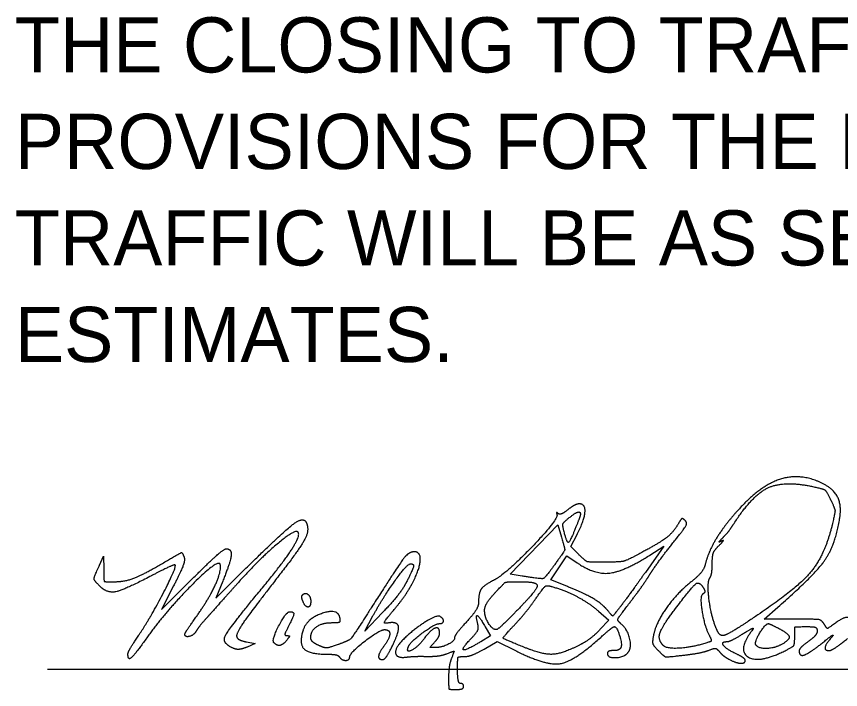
# Model space of a CAD drawing. Extents: x 0 to 34, y -7.5 to 22.
# Drawn here: x 24.421 to 26.511, y 8.312 to 10.02 of the extents above; entities that cross this region are included whole.
import ezdxf

# ---------------------------------------------------------------- set-up
doc = ezdxf.new("R2010")
doc.units = 0
doc.layers.add('SH_Data', color=7, linetype='Continuous')
doc.layers.add('SH_Text', color=7, linetype='Continuous')

msp = doc.modelspace()

# ---------------------------------------------------------------- linework, layer by layer
at = {"layer": 'SH_Data'}
msp.add_line((24.5, 8.3631), (28, 8.3631), dxfattribs=at)
at = {"layer": 'SH_Text'}
for p, q in [((25.1473, 8.5361), (25.1473, 8.5361)), ((25.074, 8.4303), (25.074, 8.4303)), ((24.7038, 8.402), (24.7038, 8.402))]:
    msp.add_line(p, q, dxfattribs=at)
for points in [[(25.7032, 8.5995), (25.6728, 8.6043), (25.7937, 8.73), (25.8032, 8.6979)], [(25.8471, 8.6544), (25.8273, 8.6743), (25.8431, 8.7054)], [(26.0277, 8.6528), (26.0627, 8.6751), (26.016, 8.609)], [(24.6314, 8.627), (24.6418, 8.6498), (24.6424, 8.6175)], [(25.8166, 8.5737), (25.7763, 8.5901), (25.7968, 8.6205), (25.8172, 8.6508), (25.8431, 8.6332)], [(24.9443, 8.5869), (24.9263, 8.5434), (25.0032, 8.6194)], [(24.8197, 8.5749), (24.7885, 8.5143), (24.866, 8.5915)], [(25.3498, 8.5073), (25.3044, 8.4598), (25.3252, 8.4984)], [(25.897, 8.5107), (25.9236, 8.4877), (25.9008, 8.4636)], [(26.3894, 8.4902), (26.3173, 8.4902), (26.352, 8.5206)], [(25.6099, 8.4709), (25.623, 8.4479), (25.5985, 8.433)], [(25.0047, 8.4325), (25.0268, 8.428), (25.006, 8.4194)], [(25.6073, 8.4144), (25.6406, 8.4334), (25.6864, 8.4105)]]:
    msp.add_lwpolyline(points, dxfattribs=at)
for points in [[(26.467, 8.8338), (26.4102, 8.8623), (26.3049, 8.8281), (26.2472, 8.7626)], [(26.239, 8.7302), (26.2861, 8.8038), (26.3666, 8.8426), (26.44, 8.8269)], [(26.44, 8.8269), (26.4676, 8.821), (26.4755, 8.8152), (26.486, 8.7931)], [(26.5088, 8.7448), (26.5142, 8.7776), (26.4942, 8.8203), (26.467, 8.8338)], [(25.8487, 8.7828), (25.843, 8.7828), (25.8297, 8.776), (25.8193, 8.7678)], [(25.8431, 8.7054), (25.8614, 8.7413), (25.8644, 8.7828), (25.8487, 8.7828)], [(26.486, 8.7931), (26.4968, 8.7704), (26.4973, 8.7609), (26.4897, 8.729)], [(25.7948, 8.7583), (25.7918, 8.7613), (25.7905, 8.7601), (25.7919, 8.7555)], [(25.8193, 8.7678), (25.8088, 8.7596), (25.7978, 8.7553), (25.7948, 8.7583)], [(25.8213, 8.7465), (25.8372, 8.7594), (25.8514, 8.764), (25.8514, 8.7563)], [(26.2472, 8.7626), (26.2136, 8.7244), (26.1756, 8.6606), (26.168, 8.6295)], [(25.0032, 8.6194), (25.0977, 8.7126), (25.1501, 8.7515), (25.157, 8.7335)], [(25.7919, 8.7555), (25.7955, 8.7438), (25.6624, 8.6049), (25.6332, 8.5899)], [(25.8099, 8.7123), (25.8058, 8.7284), (25.8084, 8.7361), (25.8213, 8.7465)], [(25.8514, 8.7563), (25.8514, 8.7543), (25.8459, 8.7389), (25.8392, 8.7221)], [(26.0861, 8.6836), (26.114, 8.7183), (26.1229, 8.7347), (26.1171, 8.7405)], [(26.1171, 8.7405), (26.1113, 8.7462), (26.1067, 8.7447), (26.1013, 8.7352)], [(26.352, 8.5206), (26.4443, 8.6012), (26.4977, 8.6776), (26.5088, 8.7448)], [(25.157, 8.7335), (25.164, 8.7155), (25.1419, 8.6722), (25.0952, 8.6118)], [(25.8392, 8.7221), (25.8249, 8.6863), (25.8171, 8.6837), (25.8099, 8.7123)], [(26.1013, 8.7352), (26.0882, 8.712), (26.055, 8.6852), (26.0075, 8.6597)], [(26.2124, 8.697), (26.2208, 8.7054), (26.2328, 8.7204), (26.239, 8.7302)], [(26.4897, 8.729), (26.4708, 8.6504), (26.3943, 8.5624), (26.278, 8.4854)], [(25.135, 8.7113), (25.1273, 8.719), (25.0363, 8.642), (24.9838, 8.5833)], [(25.0419, 8.5662), (25.0961, 8.6316), (25.1425, 8.7039), (25.135, 8.7113)], [(25.8032, 8.6979), (25.8124, 8.6669), (25.8118, 8.6645), (25.7879, 8.6312)], [(26.2086, 8.6878), (26.2024, 8.6844), (26.2041, 8.6886), (26.2124, 8.697)], [(26.0278, 8.6043), (26.0383, 8.621), (26.0646, 8.6567), (26.0861, 8.6836)], [(26.1857, 8.6324), (26.1858, 8.6515), (26.1913, 8.6659), (26.2029, 8.6772)], [(26.2029, 8.6772), (26.2123, 8.6863), (26.2149, 8.6911), (26.2086, 8.6878)], [(24.804, 8.6392), (24.8369, 8.6586), (24.8417, 8.6596), (24.846, 8.6483)], [(24.866, 8.5915), (24.9086, 8.634), (24.9477, 8.6688), (24.9529, 8.6688)], [(24.9529, 8.6688), (24.9675, 8.6688), (24.9639, 8.6346), (24.9443, 8.5869)], [(25.43, 8.6612), (25.416, 8.6612), (25.3902, 8.6276), (25.3225, 8.5215)], [(25.4251, 8.5813), (25.4438, 8.6169), (25.4466, 8.6612), (25.43, 8.6612)], [(25.8431, 8.6332), (25.8873, 8.603), (25.9615, 8.6109), (26.0277, 8.6528)], [(25.9143, 8.6348), (25.8733, 8.6346), (25.8644, 8.6372), (25.8471, 8.6544)], [(26.0075, 8.6597), (25.9701, 8.6396), (25.9529, 8.635), (25.9143, 8.6348)], [(24.6687, 8.5852), (24.6965, 8.5852), (24.7456, 8.6047), (24.804, 8.6392)], [(24.938, 8.6287), (24.9348, 8.6455), (24.8011, 8.5121), (24.7516, 8.4427)], [(24.846, 8.6483), (24.849, 8.6406), (24.8386, 8.6117), (24.8197, 8.5749)], [(25.7879, 8.6312), (25.7619, 8.5949), (25.753, 8.5916), (25.7032, 8.5995)], [(26.1794, 8.5944), (26.1828, 8.5998), (26.1857, 8.6169), (26.1857, 8.6324)], [(24.6329, 8.5735), (24.6178, 8.5887), (24.6176, 8.5968), (24.6314, 8.627)], [(24.6424, 8.6175), (24.643, 8.586), (24.6437, 8.5852), (24.6687, 8.5852)], [(24.7313, 8.4495), (24.761, 8.4937), (24.8281, 8.623), (24.8236, 8.6275)], [(24.8236, 8.6275), (24.8221, 8.6291), (24.7952, 8.6169), (24.7638, 8.6005)], [(24.8747, 8.4928), (24.9076, 8.5386), (24.9414, 8.6112), (24.938, 8.6287)], [(25.0952, 8.6118), (25.0175, 8.5114), (24.9771, 8.4531), (24.9798, 8.445)], [(25.3252, 8.4984), (25.3497, 8.5438), (25.4119, 8.6306), (25.4201, 8.6307)], [(25.4201, 8.6307), (25.4296, 8.6308), (25.4266, 8.6165), (25.4105, 8.5849)], [(26.168, 8.6295), (26.1653, 8.6184), (26.1492, 8.5983), (26.1323, 8.5849)], [(24.7638, 8.6005), (24.6945, 8.5642), (24.6512, 8.5553), (24.6329, 8.5735)], [(25.6332, 8.5899), (25.6065, 8.5763), (25.593, 8.557), (25.593, 8.5323)], [(26.016, 8.609), (25.9903, 8.5727), (25.9619, 8.5337), (25.9529, 8.5223)], [(25.9758, 8.5309), (25.9939, 8.5545), (26.0173, 8.5875), (26.0278, 8.6043)], [(26.1947, 8.4693), (26.1824, 8.5008), (26.1723, 8.5832), (26.1794, 8.5944)], [(24.9838, 8.5833), (24.9531, 8.549), (24.9178, 8.5094), (24.9052, 8.4953)], [(25.4105, 8.5849), (25.4021, 8.5684), (25.3748, 8.5335), (25.3498, 8.5073)], [(25.3786, 8.5143), (25.3954, 8.5345), (25.4163, 8.5646), (25.4251, 8.5813)], [(25.6345, 8.5567), (25.658, 8.5823), (25.6645, 8.5852), (25.6986, 8.5852)], [(25.7413, 8.5774), (25.744, 8.5731), (25.7231, 8.5458), (25.6949, 8.5166)], [(25.6986, 8.5852), (25.7195, 8.5852), (25.7387, 8.5817), (25.7413, 8.5774)], [(25.7376, 8.5416), (25.7578, 8.5704), (25.7661, 8.5768), (25.7787, 8.5731)], [(25.7787, 8.5731), (25.8144, 8.5626), (25.8721, 8.5322), (25.897, 8.5107)], [(25.9199, 8.5129), (25.9062, 8.5293), (25.8627, 8.555), (25.8166, 8.5737)], [(26.1323, 8.5849), (26.0961, 8.5563), (26.043, 8.481), (26.0367, 8.4494)], [(26.0927, 8.5176), (26.1354, 8.5736), (26.1527, 8.5865), (26.1628, 8.5702)], [(26.1628, 8.5702), (26.1673, 8.5631), (26.1669, 8.5572), (26.1619, 8.5541)], [(24.9743, 8.415), (24.9416, 8.4275), (24.9586, 8.4656), (25.0419, 8.5662)], [(25.1473, 8.5361), (25.1448, 8.5425), (25.1447, 8.5497), (25.147, 8.5521)], [(25.147, 8.5521), (25.1536, 8.5587), (25.1674, 8.5474), (25.1674, 8.5353)], [(25.6083, 8.5128), (25.6083, 8.5212), (25.6201, 8.541), (25.6345, 8.5567)], [(26.1619, 8.5541), (26.1535, 8.5489), (26.1659, 8.472), (26.1791, 8.4468)], [(25.1674, 8.5353), (25.1674, 8.5207), (25.1529, 8.5213), (25.1473, 8.5361)], [(25.593, 8.5323), (25.593, 8.5236), (25.5794, 8.5016), (25.5626, 8.4834)], [(25.6853, 8.4769), (25.7002, 8.4925), (25.7237, 8.5216), (25.7376, 8.5416)], [(25.9541, 8.4787), (25.9446, 8.4866), (25.9478, 8.4943), (25.9758, 8.5309)], [(25.074, 8.4303), (25.0677, 8.4366), (25.1048, 8.5092), (25.1144, 8.5092)], [(25.1144, 8.5092), (25.125, 8.5092), (25.1236, 8.4967), (25.1102, 8.4708)], [(25.2416, 8.4933), (25.2364, 8.5183), (25.1574, 8.4917), (25.1479, 8.4619)], [(25.3225, 8.5215), (25.2749, 8.4469), (25.2649, 8.4357), (25.2375, 8.426)], [(25.3612, 8.4801), (25.352, 8.4784), (25.3573, 8.4889), (25.3786, 8.5143)], [(25.6378, 8.4636), (25.6279, 8.4636), (25.6082, 8.4964), (25.6083, 8.5128)], [(25.6949, 8.5166), (25.6668, 8.4874), (25.6411, 8.4636), (25.6378, 8.4636)], [(25.9529, 8.5223), (25.934, 8.4983), (25.9324, 8.4978), (25.9199, 8.5129)], [(26.0617, 8.423), (26.0472, 8.4375), (26.059, 8.4734), (26.0927, 8.5176)], [(24.8482, 8.4521), (24.8482, 8.4542), (24.8602, 8.4725), (24.8747, 8.4928)], [(24.9052, 8.4953), (24.8927, 8.4813), (24.8797, 8.465), (24.8764, 8.4591)], [(25.221, 8.4813), (25.238, 8.4813), (25.2434, 8.4845), (25.2416, 8.4933)], [(25.4953, 8.4971), (25.488, 8.5016), (25.4309, 8.4664), (25.4045, 8.441)], [(25.4931, 8.4788), (25.5033, 8.4788), (25.5048, 8.4912), (25.4953, 8.4971)], [(25.5909, 8.4783), (25.585, 8.5012), (25.5949, 8.4973), (25.6099, 8.4709)], [(26.278, 8.4854), (26.2471, 8.465), (26.2176, 8.4484), (26.2124, 8.4484)], [(26.4695, 8.4777), (26.4631, 8.4878), (26.4482, 8.4902), (26.3894, 8.4902)], [(26.5325, 8.4745), (26.5395, 8.4928), (26.5194, 8.4962), (26.4981, 8.4804)], [(25.1102, 8.4708), (25.1024, 8.4556), (25.1014, 8.4484), (25.1074, 8.4484)], [(25.1674, 8.4432), (25.1674, 8.4606), (25.1966, 8.4813), (25.221, 8.4813)], [(25.3744, 8.4221), (25.3927, 8.4597), (25.3869, 8.4849), (25.3612, 8.4801)], [(25.4153, 8.4207), (25.4201, 8.4325), (25.4822, 8.4788), (25.4931, 8.4788)], [(25.4942, 8.4547), (25.4942, 8.4713), (25.472, 8.4637), (25.4555, 8.4414)], [(25.5626, 8.4834), (25.5459, 8.4653), (25.5322, 8.4471), (25.5322, 8.443)], [(25.5736, 8.4403), (25.5881, 8.4554), (25.5937, 8.4678), (25.5909, 8.4783)], [(25.7115, 8.4176), (25.6563, 8.4398), (25.6544, 8.4442), (25.6853, 8.4769)], [(25.9028, 8.4438), (25.9194, 8.4589), (25.9349, 8.4712), (25.9371, 8.4712)], [(25.9371, 8.4712), (25.9438, 8.4712), (25.958, 8.4243), (25.9535, 8.4171)], [(25.9719, 8.4052), (25.9821, 8.4175), (25.9705, 8.4651), (25.9541, 8.4787)], [(26.2124, 8.4484), (26.2072, 8.4484), (26.1992, 8.4578), (26.1947, 8.4693)], [(26.2639, 8.4534), (26.2816, 8.4646), (26.2923, 8.4688), (26.2877, 8.4629)], [(26.2961, 8.4254), (26.2922, 8.4318), (26.3205, 8.4788), (26.3282, 8.4788)], [(26.3282, 8.4788), (26.3298, 8.4788), (26.3411, 8.4735), (26.3534, 8.4672)], [(26.3534, 8.4672), (26.3792, 8.4538), (26.3823, 8.4372), (26.3611, 8.4258)], [(26.3948, 8.4447), (26.3948, 8.4699), (26.3965, 8.4712), (26.429, 8.4712)], [(26.429, 8.4712), (26.4438, 8.4712), (26.4518, 8.4673), (26.4518, 8.4603)], [(26.4981, 8.4804), (26.4791, 8.4664), (26.4767, 8.4662), (26.4695, 8.4777)], [(24.7038, 8.402), (24.7038, 8.4058), (24.7162, 8.4271), (24.7313, 8.4495)], [(24.8764, 8.4591), (24.8707, 8.4492), (24.8482, 8.4436), (24.8482, 8.4521)], [(24.9798, 8.445), (24.9813, 8.4406), (24.9925, 8.4349), (25.0047, 8.4325)], [(25.1074, 8.4484), (25.1136, 8.4484), (25.1134, 8.4451), (25.1066, 8.437)], [(25.1479, 8.4619), (25.1371, 8.4278), (25.1643, 8.4012), (25.2102, 8.4012)], [(25.187, 8.4239), (25.1762, 8.4288), (25.1674, 8.4375), (25.1674, 8.4432)], [(25.2662, 8.3945), (25.2662, 8.4043), (25.342, 8.4636), (25.3546, 8.4636)], [(25.3546, 8.4636), (25.3682, 8.4636), (25.3675, 8.4409), (25.3534, 8.4222)], [(25.5322, 8.443), (25.5322, 8.4343), (25.499, 8.418), (25.4813, 8.418)], [(25.4817, 8.4319), (25.4886, 8.4395), (25.4942, 8.4498), (25.4942, 8.4547)], [(25.6864, 8.4105), (25.764, 8.3717), (25.8351, 8.3827), (25.9028, 8.4438)], [(25.9008, 8.4636), (25.8883, 8.4503), (25.865, 8.4327), (25.849, 8.4245)], [(26.0367, 8.4494), (26.0333, 8.4326), (26.0364, 8.423), (26.0491, 8.4103)], [(26.1791, 8.4468), (26.1848, 8.4362), (26.1809, 8.4325), (26.1574, 8.426)], [(26.2234, 8.4332), (26.228, 8.4332), (26.2462, 8.4423), (26.2639, 8.4534)], [(26.2877, 8.4629), (26.2489, 8.4128), (26.3027, 8.3768), (26.3682, 8.409)], [(26.3682, 8.409), (26.3898, 8.4196), (26.3948, 8.4264), (26.3948, 8.4447)], [(26.4518, 8.4603), (26.4518, 8.4543), (26.4416, 8.4421), (26.429, 8.4332)], [(26.4662, 8.4309), (26.4855, 8.4464), (26.4952, 8.4521), (26.4879, 8.4436)], [(26.4879, 8.4436), (26.4731, 8.4264), (26.4705, 8.4104), (26.4825, 8.4104)], [(24.7516, 8.4427), (24.7204, 8.3989), (24.7038, 8.3848), (24.7038, 8.402)], [(25.1066, 8.437), (25.0968, 8.4251), (25.0822, 8.4221), (25.074, 8.4303)], [(25.2375, 8.426), (25.213, 8.4173), (25.2024, 8.4169), (25.187, 8.4239)], [(25.3534, 8.4222), (25.3405, 8.4052), (25.3387, 8.3876), (25.3499, 8.3876)], [(25.4045, 8.441), (25.3808, 8.4183), (25.3844, 8.3904), (25.4106, 8.3939)], [(25.4555, 8.4414), (25.4393, 8.4195), (25.4083, 8.4035), (25.4153, 8.4207)], [(25.4813, 8.418), (25.4702, 8.418), (25.4702, 8.4192), (25.4817, 8.4319)], [(25.5985, 8.433), (25.5613, 8.4103), (25.5485, 8.4141), (25.5736, 8.4403)], [(25.849, 8.4245), (25.8058, 8.4022), (25.7559, 8.3997), (25.7115, 8.4176)], [(26.1574, 8.426), (26.1253, 8.4171), (26.0694, 8.4153), (26.0617, 8.423)], [(26.245, 8.4028), (26.2209, 8.4141), (26.2074, 8.4332), (26.2234, 8.4332)], [(26.3611, 8.4258), (26.3425, 8.4159), (26.3022, 8.4156), (26.2961, 8.4254)], [(26.429, 8.4332), (26.4165, 8.4242), (26.4062, 8.4137), (26.4062, 8.4098)], [(26.4062, 8.4098), (26.4062, 8.3947), (26.4328, 8.404), (26.4662, 8.4309)], [(26.4825, 8.4104), (26.4868, 8.4104), (26.5076, 8.424), (26.5287, 8.4408)], [(25.006, 8.4194), (24.9945, 8.4147), (24.9803, 8.4127), (24.9743, 8.415)], [(25.2102, 8.4012), (25.2243, 8.4012), (25.2378, 8.3982), (25.2401, 8.3944)], [(25.3499, 8.3876), (25.3542, 8.3876), (25.3652, 8.4031), (25.3744, 8.4221)], [(25.4614, 8.3957), (25.4788, 8.3954), (25.5018, 8.3984), (25.5124, 8.4024)], [(25.5124, 8.4024), (25.5307, 8.4094), (25.5313, 8.4088), (25.5243, 8.3906)], [(25.5569, 8.3953), (25.5663, 8.3953), (25.589, 8.4039), (25.6073, 8.4144)], [(25.9346, 8.4104), (25.9265, 8.4104), (25.9198, 8.4069), (25.9198, 8.4028)], [(25.9198, 8.4028), (25.9198, 8.3916), (25.9622, 8.3935), (25.9719, 8.4052)], [(25.9535, 8.4171), (25.9512, 8.4134), (25.9427, 8.4104), (25.9346, 8.4104)], [(26.0491, 8.4103), (26.0642, 8.3952), (26.0708, 8.3939), (26.1114, 8.3985)], [(26.1114, 8.3985), (26.1364, 8.4014), (26.1655, 8.407), (26.1761, 8.411)], [(26.1761, 8.411), (26.1904, 8.4164), (26.1975, 8.4156), (26.2039, 8.4077)], [(26.2039, 8.4077), (26.2086, 8.4018), (26.2193, 8.3933), (26.2276, 8.3887)], [(26.2693, 8.3857), (26.2692, 8.3888), (26.2582, 8.3965), (26.245, 8.4028)], [(25.2401, 8.3944), (25.2456, 8.3855), (25.2662, 8.3855), (25.2662, 8.3945)], [(25.4106, 8.3939), (25.4211, 8.3952), (25.4439, 8.3961), (25.4614, 8.3957)], [(25.5243, 8.3906), (25.5203, 8.38), (25.517, 8.3579), (25.517, 8.3415)], [(25.5398, 8.361), (25.5398, 8.3913), (25.5417, 8.3952), (25.5569, 8.3953)], [(26.2276, 8.3887), (26.2452, 8.3791), (26.2695, 8.3773), (26.2693, 8.3857)], [(25.5474, 8.3268), (25.5433, 8.3268), (25.5398, 8.3422), (25.5398, 8.361)], [(25.517, 8.3415), (25.517, 8.3146), (25.519, 8.3116), (25.536, 8.3116)], [(25.536, 8.3116), (25.5465, 8.3116), (25.555, 8.315), (25.555, 8.3192)], [(25.555, 8.3192), (25.555, 8.3233), (25.5516, 8.3268), (25.5474, 8.3268)]]:
    msp.add_open_spline(points, degree=2, dxfattribs=at)

# ---------------------------------------------------------------- texts
for s, p in [('THE CLOSING TO TRAFFIC OF THE HIGHWAY AND THAT ', (24.4169, 9.8779)), ('PROVISIONS FOR THE MAINTENANCE AND SAFETY OF', (24.4169, 9.6329)), ('TRAFFIC WILL BE AS SET FORTH ON THE PLANS AND', (24.4169, 9.3879)), ('ESTIMATES.', (24.4169, 9.1429))]:
    msp.add_text(s, height=0.14, dxfattribs=at).set_placement(p)

doc.saveas('drawing.dxf')
